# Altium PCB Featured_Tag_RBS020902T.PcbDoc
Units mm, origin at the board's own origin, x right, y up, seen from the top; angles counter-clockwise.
Board outline 33.22 x 33.22 mm, 2 copper layers (Top Layer, Bottom Layer); 37 components, 34 nets, 164 pads, 29 vias.
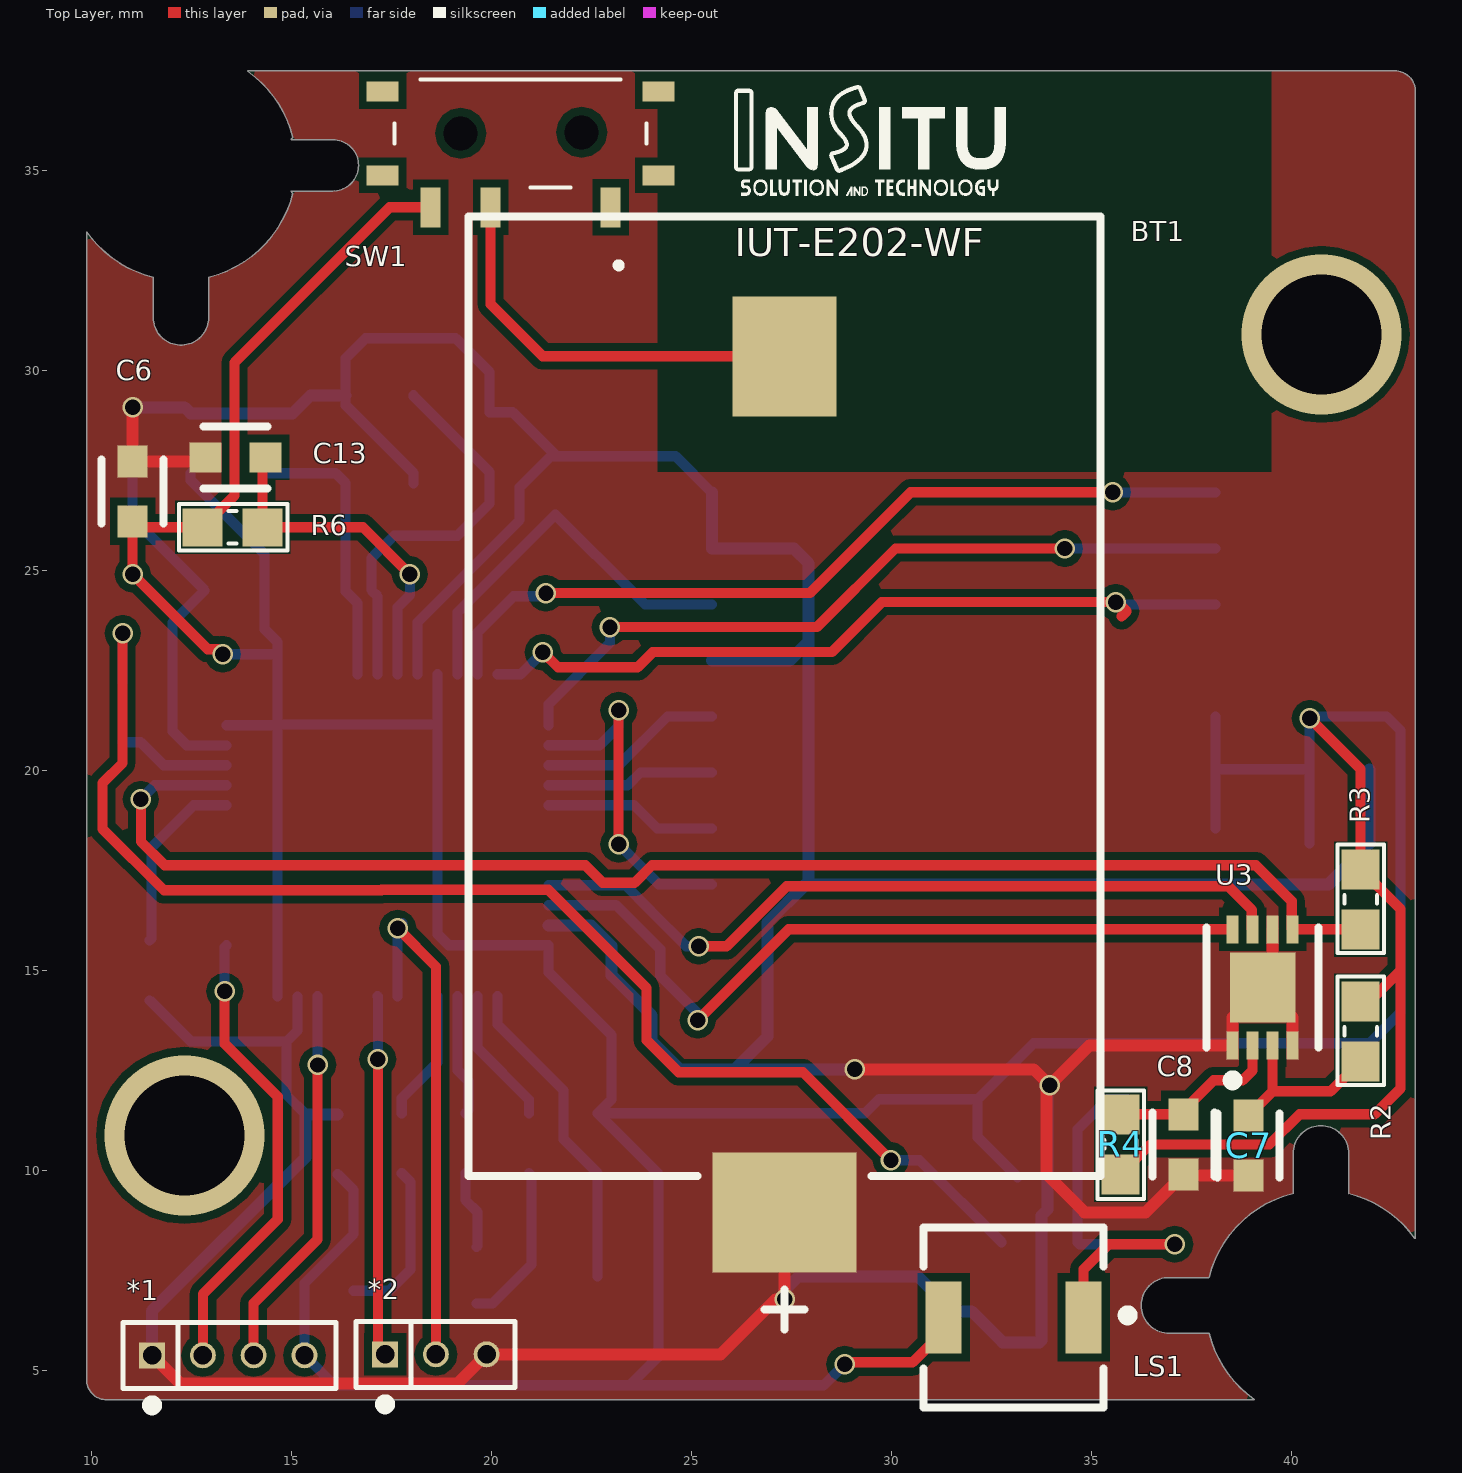
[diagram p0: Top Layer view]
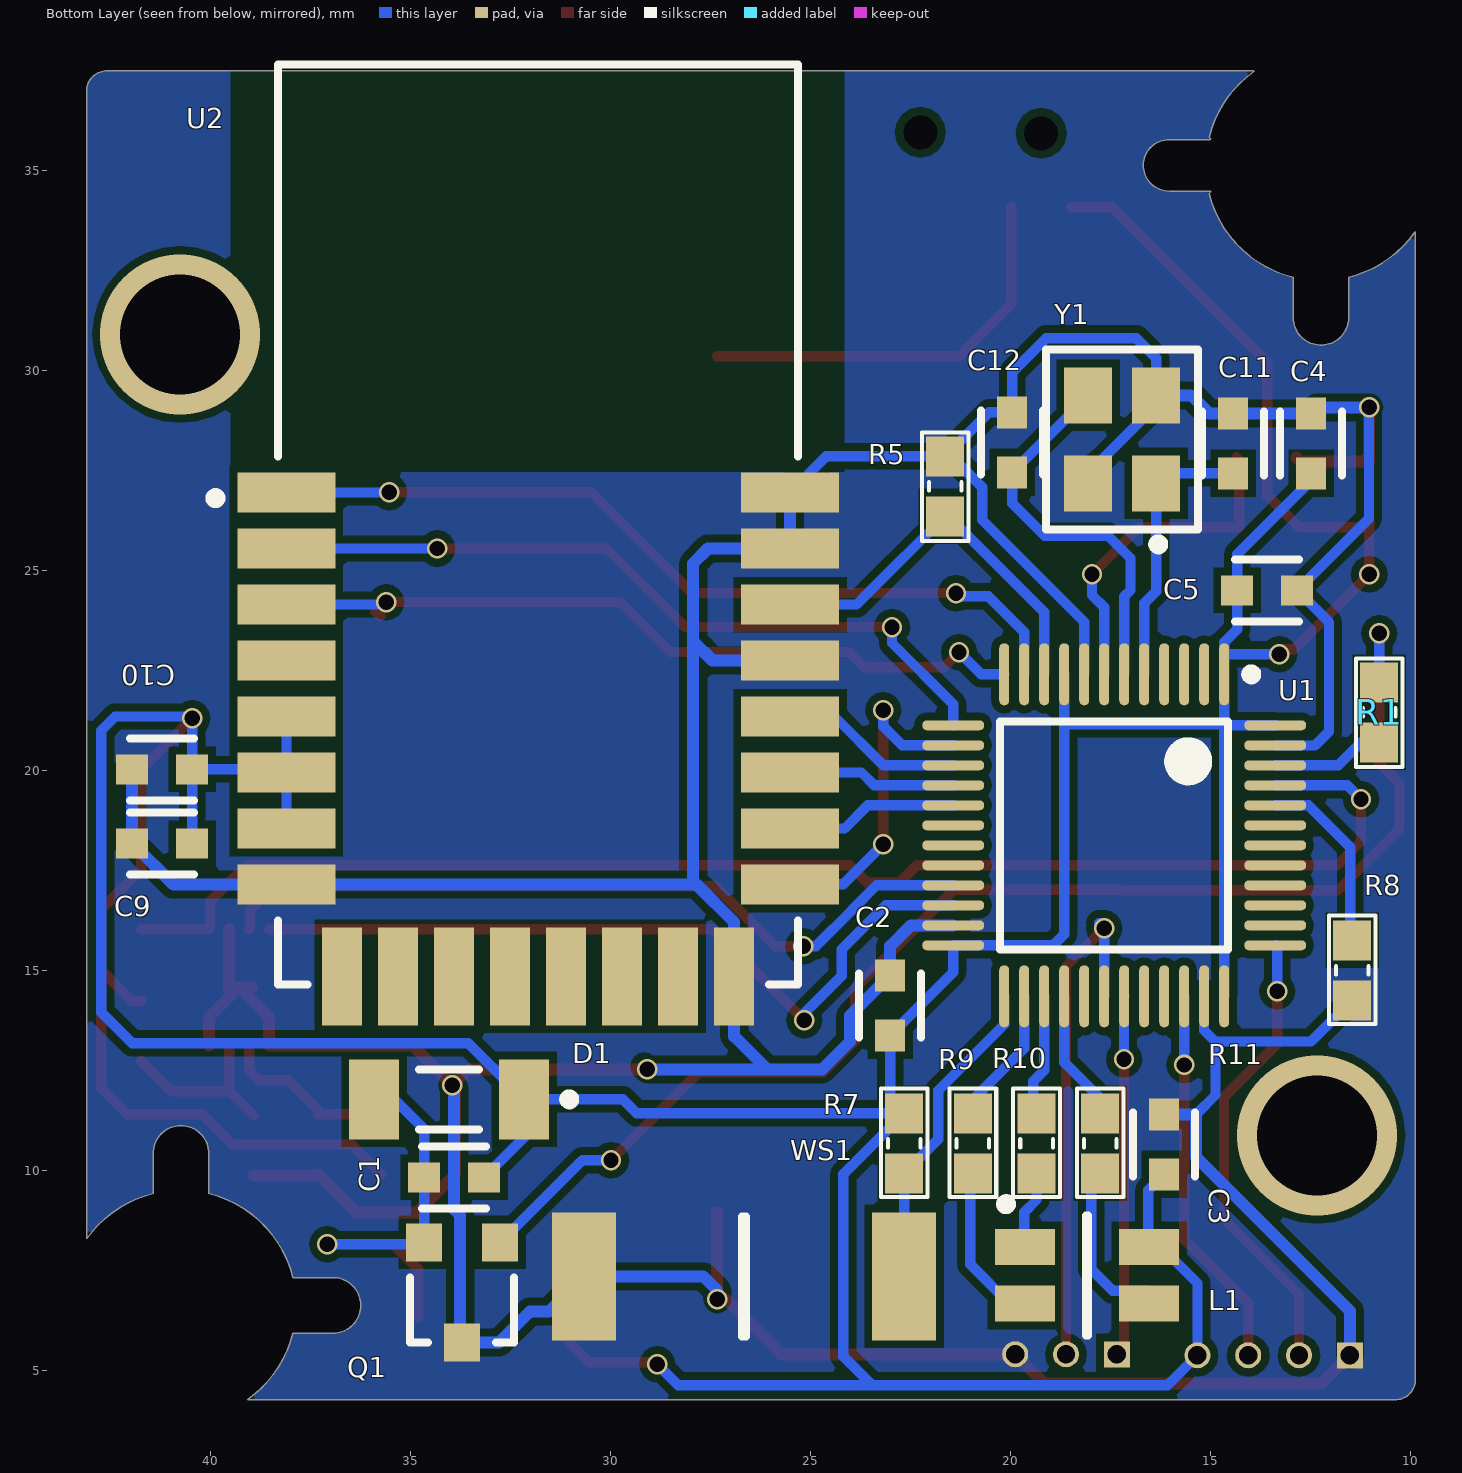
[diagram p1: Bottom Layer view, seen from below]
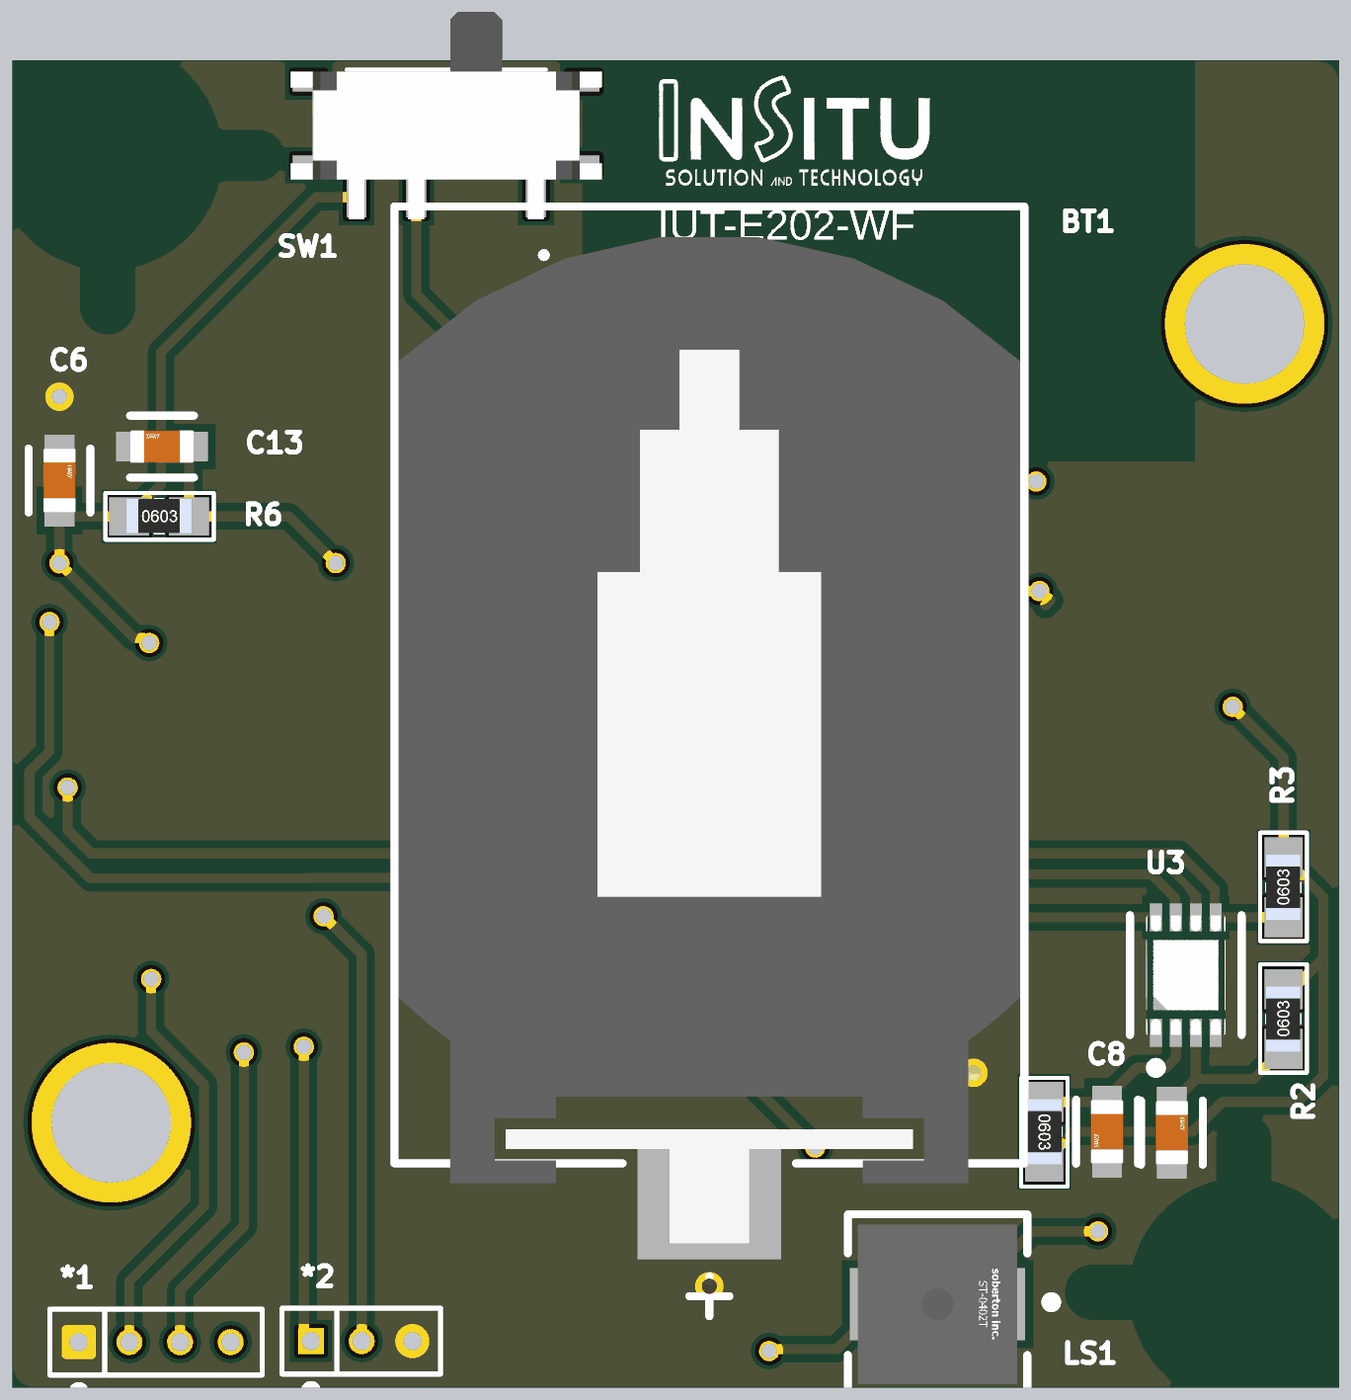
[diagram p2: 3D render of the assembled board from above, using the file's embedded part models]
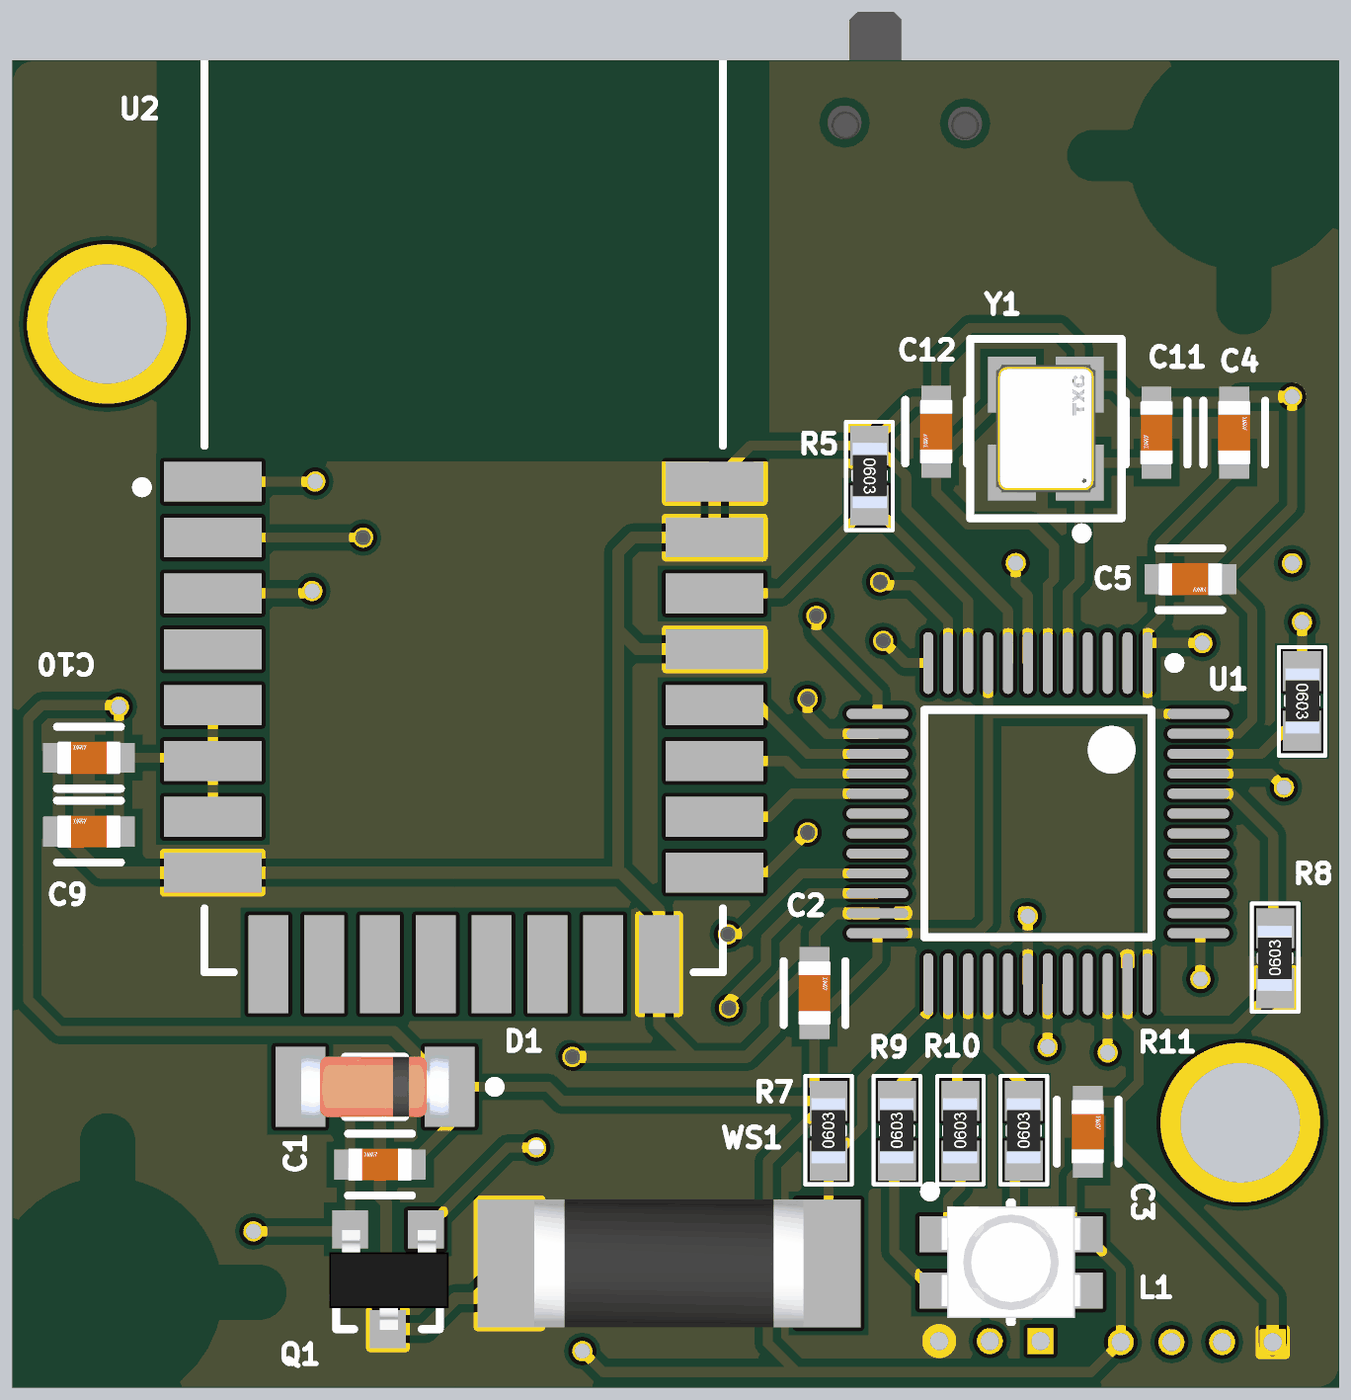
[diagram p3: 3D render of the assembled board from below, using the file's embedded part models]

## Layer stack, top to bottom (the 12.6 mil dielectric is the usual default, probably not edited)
Top Solder: solder mask 0.0102, Solder Resist, Dk 3.5
Top Layer: signal copper 0.0356
Dielectric 1: dielectric 0.32, FR-4, Dk 4.8
Bottom Layer: signal copper 0.0356
Bottom Solder: solder mask 0.0102, Solder Resist, Dk 3.5

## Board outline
9.871,4.769 ccw(c10.377,4.769) 10.377,4.263 10.378,4.263 39.055,4.263 39.06,4.275 cw(c40.732,6.624) 37.936,5.923 37.929,5.928 36.935,5.928 36.934,5.928 cw(c36.935,6.624) 36.935,7.319 37.929,7.319 37.936,7.325 cw(c40.732,6.624) 40.031,9.42 40.037,9.427 40.037,10.421 40.037,10.422 cw(c40.732,10.421) 41.428,10.421 41.428,9.427 41.433,9.42 cw(c40.732,6.624) 43.081,8.296 43.093,8.299 43.093,36.978 43.093,36.979 ccw(c42.587,36.979) 42.587,37.485 13.908,37.485 13.904,37.472 cw(c12.232,35.124) 15.028,35.828 cw(c7.741,41.518) 14.989,35.778 14.994,35.767 16.03,35.767 cw(c16.03,35.124) 16.673,35.124 cw(c16.03,35.124) 16.03,34.48 14.994,34.48 14.989,34.47 cw(c7.719,28.712) 15.028,34.42 cw(c12.232,35.124) 12.933,32.327 12.928,32.321 12.928,31.326 cw(c12.232,31.326) 11.537,31.326 11.537,32.321 11.531,32.327 cw(c12.232,35.124) 9.884,33.452 9.871,33.448

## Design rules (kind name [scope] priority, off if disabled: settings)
Clearance [All] p1: gap=0.2 ignorepadtopadclearanceinfootprint=FALSE
HoleSize [All] p1: absolutevalues=TRUE maxlimit=6 minlimit=0.102 maxpercent=80.000 minpercent=20.000
HoleToHoleClearance [Istext] p1: gap=0.254 allowstackedmicrovias=TRUE
MinimumSolderMaskSliver [TextHeight] p1: minsoldermaskwidth=0.254
PolygonConnect [All] p1: connectstyle=Direct reliefconductorwidth=0.254 reliefentries=4 polygonreliefangle="90 Angle" airgapwidth=0.254
RoutingVias [All] p1: holewidth=0.46 width=0.46 viastyle="Through Hole" minholewidth=0.46 minwidth=0.46 maxholewidth=0.46 maxwidth=0.46
SilkToSilkClearance [TextHeight] p1: silktosilkclearance=0.254
SilkToSolderMaskClearance [IsText] p1: minsilkscreentomaskgap=0.15 clearancetoexposedcopper=TRUE
SolderMaskExpansion [All] p1: expansion=0.102
Width [All] p1: maxlimit=0.9 minlimit=0.2 preferedwidth=0.6
25 further rules are at their usual default settings.

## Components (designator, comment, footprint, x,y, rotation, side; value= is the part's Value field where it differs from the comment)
*1 "JP 1x7 1.27mm" "JP 1x4 1.27mm" 11.485,5.375 r0 top
*2 "JP 1x3 1.27mm" "JP 1x3 1.27mm" 17.335,5.4 r0 top
BT1 "S8421-45R" FP-S8421-45R-MFG 27.325,21.85 r0 top
C1 "100pF" FP-0603-L_1_6_0_15-W_0_81-MFG 33.9,9.825 r0 bottom
C2 "100nF" FP-0603-L_1_6_0_15-W_0_81-MFG 23,14.125 r90 bottom
C3 "100nF" FP-0603-L_1_6_0_15-W_0_81-MFG 16.15,10.65 r90 bottom
C4 "100nF" FP-0603-L_1_6_0_15-W_0_81-MFG 12.475,28.175 r90 bottom
C5 "100nF" FP-0603-L_1_6_0_15-W_0_81-MFG 13.575,24.5 r180 bottom
C6 "4.7uF" FP-0603-L_1_6_0_15-W_0_81-MFG 11.025,26.975 r90 top
C7 "1uF" FP-0603-L_1_6_0_15-W_0_81-MFG 38.925,10.625 r90 top
C8 "10nF" FP-0603-L_1_6_0_15-W_0_81-MFG 37.3,10.65 r270 top
C9 "10uF" FP-0603-L_1_6_0_15-W_0_81-MFG 41.2,18.175 r0 bottom
C10 "100nF" FP-0603-L_1_6_0_15-W_0_81-MFG 41.2,20.025 r0 bottom
C11 "12pF" FP-0603-L_1_6_0_15-W_0_81-MFG 14.425,28.175 r270 bottom
C12 "12pF" FP-0603-L_1_6_0_15-W_0_81-MFG 19.95,28.2 r270 bottom
C13 "100nF" FP-0603-L_1_6_0_15-W_0_81-MFG 13.597,27.825 r180 top
D1 "LL4148-GS18" SOD-80 34.025,11.775 r0 bottom
L1 "LED 3528" "LED RGB 3528" 18.075,7.375 r180 bottom
LS1 "ST-0402T" FP-ST-0402T-MFG 33.05,6.325 r180 top value=17O
Q1 "HF" SOT23 33.7,6.95 r0 bottom value=C9014
R1 "1k" "tro smd 0603" 10.775,21.45 r270 bottom
R2 "1k" "tro smd 0603" 41.725,13.475 r90 top
R3 "4.7K" "tro smd 0603" 41.725,16.775 r90 top
R4 "1k" "tro smd 0603" 35.725,10.65 r270 top
R5 "10k" "tro smd 0603" 21.625,27.1 r270 bottom
R6 "10k" "tro smd 0603" 13.525,26.075 r0 top
R7 "10k" "tro smd 0603" 22.65,10.675 r90 bottom
R8 "10k" "tro smd 0603" 11.45,15 r90 bottom
R9 "100R" "tro smd 0603" 20.934,10.675 r90 bottom
R10 "150R" "tro smd 0603" 19.343,10.675 r90 bottom
R11 "100R" "tro smd 0603" 17.751,10.675 r90 bottom
SW1 "MSK-12C02" sw_msk_12c02 25.627,38.262 r180 top
U1 "STM32F103C8T6" STM-LQFP48_L 17.4,18.375 r270 bottom
U2 "DWM1000" DECW-DWM1000-24_V 31.8,26.145 r180 bottom
U3 "MAX17043G+T" FP-T823-1-MFG 39.275,14.575 r90 top
WS1 "RBS020902T" RBS020902T 26.65,7.35 r0 bottom
Y1 "8MHz" FP-7M-MFG 17.2,28.275 r90 bottom

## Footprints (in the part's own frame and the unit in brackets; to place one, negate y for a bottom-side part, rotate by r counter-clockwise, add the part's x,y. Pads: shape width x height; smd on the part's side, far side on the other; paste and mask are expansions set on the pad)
DECW-DWM1000-24_V [mm] "SMD, 24-Leads, Body 23x13mm, Pitch 1.4mm"
  rect 2.45x1 smd: 1(-6.295,0.8) 2(-6.295,-0.6) 3(-6.295,-2) 4(-6.295,-3.4) 5(-6.295,-4.8) 6(-6.295,-6.2) 7(-6.295,-7.6) 8(-6.295,-9) 17(6.295,-9) 18(6.295,-7.6) 19(6.295,-6.2) 20(6.295,-4.8) 21(6.295,-3.4) 22(6.295,-2) 23(6.295,-0.6) 24(6.295,0.8)
  rect 1x2.45 smd: 9(-4.9,-11.295) 10(-3.5,-11.295) 11(-2.1,-11.295) 12(-0.7,-11.295) 13(0.7,-11.295) 14(2.1,-11.295) 15(3.5,-11.295) 16(4.9,-11.295)
  silkscreen extent -8.2,-11.5 6.5,11.5, body extent -6.5,-11.5 6.5,11.5, height 4
FP-7M-MFG [mm]
  rect 1.4x1.2 smd paste+0 mask+0: 1(-1.1,-0.85) 2(1.1,-0.85) 3(1.1,0.85) 4(-1.1,0.85)
  silkscreen extent -2.75,-1.9 2.25,1.9, body extent -1.6,-1.25 1.6,1.25, height 0.8
FP-0603-L_1_6_0_15-W_0_81-MFG [mm]
  rect 0.8x0.75 smd paste+0 mask+0: 1(-0.75,0) 2(0.75,0)
  silkscreen extent -0.8,-0.77 0.8,0.77, body extent -0.8,-0.4 0.8,0.41, height 0.9
FP-S8421-45R-MFG [mm]
  rect 2.6x3 smd paste+0 mask+0: 1(0,8.5)
  rect 3.6x3 smd paste+0 mask+0: 2(0,-12.9)
  silkscreen extent -7.9,-15.83 7.9,12, body extent -8,-14.5 8,12.09, height 0.25
FP-ST-0402T-MFG [mm]
  rect 0.9x1.8 smd paste+0 mask+0: 1(-1.75,0) 2(1.75,0)
  silkscreen extent -2.98,-2.25 2.25,2.25, body extent -2.35,-2.35 2.35,2.35, height 0.25
FP-T823-1-MFG [mm]
  rect 0.7x0.3 smd paste+0 mask+0: 1(-1.45,0.75) 2(-1.45,0.25) 3(-1.45,-0.25) 4(-1.45,-0.75) 5(1.45,-0.75) 6(1.45,-0.25) 7(1.45,0.25) 8(1.45,0.75)
  rect 1.75x1.63 smd paste+0 mask+0: 9(0,0)
  silkscreen extent -2.45,-1.4 1.5,1.4, body extent -1.9,-1.12 1.9,1.12, height 0.25
"JP 1x3 1.27mm" [mm]
  rect 0.65x0.65 hole 0.46: 1(0,0)
  round 0.65 hole 0.46: 2(1.27,0) 3(2.54,0)
  silkscreen extent -0.73,-1.37 3.25,0.82
"JP 1x4 1.27mm" [mm]
  rect 0.65x0.65 hole 0.46: 1(0.025,0)
  round 0.65 hole 0.46: 2(1.295,0) 2(3.835,0) 3(2.565,0)
  silkscreen extent -0.7,-1.37 4.62,0.82
"LED RGB 3528" [mm] "Chip LED, 4-Leads, Body 2.8x3.5mm (max), Pitch 1.42mm, IPC Medium Density"
  rect 1.5x0.9 smd: 1(1.55,0.707) 2(1.55,-0.71) 3(-1.55,0.707) 4(-1.55,-0.707)
  silkscreen extent -2.16,-1.5 0.03,1.9, body extent -1.75,-1.4 1.75,1.4, height 1.87
RBS020902T [mm] "SENSOR SWITCH, 2-Leads, Body 6.75x3.20mm, IPC Medium Density"
  rect 1.6x3.2 smd: 1(-4,0) 2(4,0)
  Top Layer pour cut-out: 0.05,3.35
  silkscreen extent -0.05,-1.5 0.05,1.5, body extent -3.37,-1.6 3.38,1.6, height 3.2
SOD-80 [mm]
  rect 1.25x2 smd: 1(-1.875,0) 2(1.875,0)
  silkscreen extent -3.12,-0.75 0.75,0.75, body extent -1.85,-0.78 1.85,0.78, height 1.6
SOT23 [mm] "SOT23"
  rect 0.9x0.95 smd: 1(-0.95,-1.25) 2(0,1.25)
  rect 0.9x0.95 smd mask+0: 3(0.95,-1.25)
  silkscreen extent -1.3,-0.38 1.3,1.25, body extent -1.52,-1.23 1.48,1.27, height 1.06
STM-LQFP48_L [mm] "QFP, 48-Leads, Body 7x7mm, Pitch 0.5mm, IPC High Density"
  oval 1.55x0.25 smd: 1(-4.025,2.75) 2(-4.025,2.25) 3(-4.025,1.75) 4(-4.025,1.25) 5(-4.025,0.75) 6(-4.025,0.25) 7(-4.025,-0.25) 8(-4.025,-0.75) 9(-4.025,-1.25) 10(-4.025,-1.75) 11(-4.025,-2.25) 12(-4.025,-2.75) 25(4.025,-2.75) 26(4.025,-2.25) 27(4.025,-1.75) 28(4.025,-1.25) 29(4.025,-0.75) 30(4.025,-0.25) 31(4.025,0.25) 32(4.025,0.75) 33(4.025,1.25) 34(4.025,1.75) 35(4.025,2.25) 36(4.025,2.75)
  oval 0.25x1.55 smd: 13(-2.75,-4.025) 14(-2.25,-4.025) 15(-1.75,-4.025) 16(-1.25,-4.025) 17(-0.75,-4.025) 18(-0.25,-4.025) 19(0.25,-4.025) 20(0.75,-4.025) 21(1.25,-4.025) 22(1.75,-4.025) 23(2.25,-4.025) 24(2.75,-4.025) 37(2.75,4.025) 38(2.25,4.025) 39(1.75,4.025) 40(1.25,4.025) 41(0.75,4.025) 42(0.25,4.025) 43(-0.25,4.025) 44(-0.75,4.025) 45(-1.25,4.025) 46(-1.75,4.025) 47(-2.25,4.025) 48(-2.75,4.025)
  silkscreen extent -4.15,-2.85 2.85,3.55, body extent -3.5,-3.5 3.5,3.5, height 1.6
sw_msk_12c02 [mm]
  rect 0.5x1 smd: A1(2.652,4.187) B1(5.652,4.187) C1(7.152,4.187)
  round 0.425 hole 0.85 unplated: MH1(3.378,2.311) MH2(6.402,2.337)
  rect 0.8x0.5 smd: MP1(8.352,3.387) MP2(8.352,1.287) MP3(1.452,1.287) MP4(1.452,3.387)
  silkscreen extent 1.75,0.99 8.05,5.69, body extent 1,-0.46 8.8,4.74, height 1.46
"tro smd 0603" [mm] "Chip Capacitor, 2-Leads, Body 1,60x0,80mm, IPC Medium Density"
  rect 1x0.95 smd mask+0.076: 1(-0.75,0) 2(0.75,0)
  silkscreen extent -1.35,-0.58 1.37,0.58, body extent -0.82,-0.42 0.82,0.43, height 0.44

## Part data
BT1: library part CMP-2000-07028-3, "BATTERY HOLDER COIN 20MM SMD", Case/Package=SMD/SMT, Max Operating Temperature=105°C, Min Operating Temperature=-40°C, Package Quantity=500
C1 C2 C3 C4 C5 C6 C7 C8 C9 C10 C11 C12 C13: library part CMP-2006-04515-2, "General Purpose Ceramic Capacitor, 0603, 33nF, 5%, X7R, 15%, 16V", Capacitance=33nF, Case/Package=0603, Case Code (Metric)=1608, Dielectric=X7R, Max Operating Temperature=125°C, Min Operating Temperature=-55°C, Package Quantity=4000, Tolerance=5%, Voltage Rating=16V
D1: "Vishay LL4148-GS18 Switching Diode, 300mA, 2-Pin MiniMELF", Manufacturer_Name=Vishay, Mouser Part Number=78-LL4148-GS18
L1: library part "LED 3528 RGB", "Dán"
LS1: library part CMP-247804-000001-1, "AUDIO MAGNETIC XDCR 2-4V SMD", Current=90mA, Frequency=4kHz, Manufacturer="Soberton Inc.", Max Supply Voltage=4V, Min Supply Voltage=2V, Operating Supply Voltage=3V, Resistance=17O, Temperature="-30°C to +70°C", Temperature Range High=+70°C, Temperature Range Low=-30°C
Q1: library part "C1815 HF SMD", "NPN transistor"
R1 R2 R3 R4: library part "Tro 0603 5% 1k", "Dán"
R5 R6 R7 R8: library part "Tro 0603 5% 10k", "Dán"
R9 R11: library part "Tro 0603 5% 100R", "Dán"
R10: library part "Tro 0603 5% 150R", "Dán"
U1: library part CMP-0237-00215-3, "ARM Cortex-M3 32-bit MCU, 64 KB Flash, 20 KB Internal RAM, 37 I/Os, 48-pin LQFP, -40 to 85 degC, Tray", I/Os (High Current)=37, Operating Frequency(F) (Processor speed) (MHz)=72, Supply Voltage(Vcc) min (V)=2
U2: library part CMP-2000-05094-1, "DW M1000 IEEE 802.15.4 -2011 UWB Transceiver Module", Current - Receiving=64mA, Current - Transmitting=31mA, Frequency=3.5GHz~6.5GHz, Manufacturer=Decawave, Operating Temperature=-40degC~85degC, Package / Case=Module, Power - Output=-, Standard Package=500, Voltage - Supply=2.8V~3.6V
U3: library part CMP-05715-000066-1, "IC 2-WIRE FG MODEL GAUGE LO BATT", Manufacturer=Maxim, Max Supply Voltage=4.5V, Min Supply Voltage=2.5V, Nominal Supply Current=50uA, Package=T823-1, Temperature="-20°C to +70°C", Temperature Range High=+70°C, Temperature Range Low=-20°C
Y1: library part CMP-18717-000290-1, "Crystal 26MHz, 30ppm, 18pF, 50O", Case/Package=SMD/SMT, ESR (Equivalent Series Resistance)=60R, Frequency=26MHz, Frequency Stability=30ppm, Load Capacitance=18pF, Max Operating Temperature=70°C, Min Operating Temperature=-20°C, Package Quantity=3000

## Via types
v1: diameter 0.508, hole 0.381, Top Layer to Bottom Layer, 27 vias
v2: diameter 4, hole 3, Top Layer to Bottom Layer, 2 vias

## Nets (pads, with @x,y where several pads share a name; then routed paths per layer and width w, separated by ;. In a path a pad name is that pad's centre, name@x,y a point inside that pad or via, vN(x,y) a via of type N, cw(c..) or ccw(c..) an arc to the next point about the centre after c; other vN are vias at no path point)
+3: *1.2@15.32,5.375 C1.1 C2.1 C3.1 C4.1 C5.1 C6.1 C9.1 C10.1 D1.1 L1.1 LS1.2 R2.2 R3.2 R4.2 R6.1 R7.2 SW1.C1 U1.1 U1.9 U1.24 U1.36 U1.48 U2.5 U2.6 U2.7 | length 143.1
  Top Layer w0.254: v1@13.325,22.9 v1(13.275,22.9) 13.15,23.025 12.9,23.025 v1(11.025,24.9) C6.1 11.175,26.075 R6.1 13.574,26.874 13.574,30.199 17.45,34.075 SW1.C1 ; v1(28.825,5.15) 28.875,5.2 30.525,5.2 31.3,5.975 LS1.2 ; R4.2 36.473,10.648 39.448,10.648 40.2,11.4 42.075,11.4 42.725,12.05 42.725,15 ; v1(40.45,21.3) 41.725,20.025 R3.2 42.725,16.525 42.725,15 ; R2.2 41.95,14.225 42.725,15
  Bottom Layer w0.254: C4.1 12.475,27.25 14.325,25.4 C5.1 14.325,23.525 14.65,23.2 U1.1@14.65,22.875 ; v1(13.275,22.9) 14.625,22.9 U1.1@14.65,22.875 ; U1.48 14.65,21.125 ; U1.36 14.65,21.125 ; C3.1 16.55,9.5 16.55,8.408 15.32,7.178 15.32,5.375 16.07,4.625 23.45,4.625 ; U1.9 18.65,21.145 ; v1(28.825,5.15) 28.3,4.625 23.45,4.625 ; C1.1 32.15,10.825 D1.1 ; U2.7 U2.6 ; U2.5 U2.6 ; C9.1 C10.1 ; 14.65,21.125 14.65,21.145 ; 14.65,21.145 U1.1 U1.1@14.65,22.875 ; 14.65,21.145 18.65,21.145 ; 18.65,21.145 18.65,15.9 18.925,15.625 U1.24 21.425,14.95 C2.1 23,11.775 R7.2 ; R7.2 29.335,11.425 29.685,11.775 D1.1 ; R7.2 24.175,9.9 24.175,5.35 23.45,4.625 ; D1.1 33.55,13.175 41.95,13.175 42.725,13.95 42.725,20.995 42.375,21.345 40.495,21.345 v1(40.45,21.3) C10.1 ; U2.6 38.175,20.025 C10.1
BLUE: R11.2 U1.28 | length 3.3
  Bottom Layer w0.254: R11.2 17.751,11.801 18.65,12.7 U1.28
BOOT0: R8.2 U1.44 | length 4.7
  Bottom Layer w0.254: R8.2 11.5,15.8 11.5,18.075 12.55,19.125 U1.44
BUZZER: R1.2 U1.46 | length 2.8
  Bottom Layer w0.254: R1.2 11.225,20.7 11.8,20.125 U1.46
CLK: *1.2@12.78,5.375 U1.37 | length 11.6
  Top Layer w0.254: *1.2@12.78,5.375 12.78,6.905 14.652,8.777 14.652,11.839 13.325,13.166 v1(13.325,14.475)
  Bottom Layer w0.254: v1(13.325,14.475) 13.325,15.575 U1.37
DIO: *1.3 U1.34 | length 9.6
  Top Layer w0.254: *1.3 14.05,6.675 15.65,8.275 v1(15.65,12.635)
  Bottom Layer w0.254: v1@15.65,12.635 U1.34
GND: *1.1 *2.3 BT1.2 C2.2 C3.2 C4.2 C5.2 C6.2 C7.1 C8.2 C9.2 C10.2 C11.1 C12.1 C13.2 Q1.2 R5.1 R8.1 U1.8 U1.23 U1.35 U1.47 U2.8 U2.16 U2.21 U2.23 U2.24 U3.1 U3.4 U3.6 U3.9 WS1.2 Y1.2 Y1.4 | length 160.6
  Top Layer w0.3: v1(11.025,29.075) 11.025,27.875 11.1,27.8 C6.2 12.747,27.725 C13.2 ; *1.1 12.21,4.675 19.15,4.675 *2.3 25.725,5.4 27.1,6.775 v1(27.325,6.775) BT1.2 ; v1(29.075,12.525) 33.55,12.525 v1(33.95,12.125) ; C7.1 37.325,9.875 C8.2 36.35,8.95 34.825,8.95 33.875,9.9 33.875,12.05 v1(33.95,12.125) ; U3.9@38.95,14.575 U3.9 ; U3.6 39.525,14.575 U3.9 ; U3.4 40.025,13.825 U3.9 ; v1(33.95,12.125) 34.95,13.125 U3.1 38.525,13.825 U3.9
  Bottom Layer w0.25: v1(11.025,29.075) 11.025,26.3 C5.2 12.025,23.7 12.025,20.975 12.375,20.625 U1.47 ; R8.1 12.475,13.225 14.868,13.225 ; U1.35 15.15,13.493 14.875,13.218 14.868,13.225 ; 15.35,11.4 14.868,11.882 14.868,13.225
  Bottom Layer w0.254: Y1.4 18.05,27.425 16.35,29.125 Y1.2 16.35,30.3 16.85,30.8 19.1,30.8 19.95,29.95 C12.1 20.525,28.95 R5.1 ; U1.8 18.15,23.709 20.7,26.259 20.7,27.075 21.475,27.85 R5.1 ; U2.24 24.6,27.85 R5.1
  Bottom Layer w0.3: v1(11.025,29.075) 12.325,29.075 C4.2 C11.1 15.025,28.925 15.475,29.375 Y1.2 ; *1.1 11.51,6.485 15.35,10.325 15.35,11.4 C3.2 ; U1.23 22.481,16.125 23,15.606 C2.2 24,13.875 24,13.225 24.7,12.525 26.075,12.525 ; U2.21 27.445,22.745 27.925,23.225 ; U2.24 U2.23 27.555,25.545 27.925,25.175 27.925,23.225 ; v1(27.325,6.775) 27.325,7 27.675,7.35 WS1.2 31.525,6.475 32,6.475 32.775,5.7 Q1.2 33.75,5.75 33.75,8.875 33.9,9.025 33.9,12.075 v1(33.95,12.125) ; v1@29.15,12.6 v1(29.075,12.525) 26.075,12.525 ; C10.2 C9.2 40.92,17.145 U2.8 28,17.145 ; 26.075,12.525 26.9,13.35 U2.16 26.9,16.2 27.845,17.145 28,17.145 ; 27.925,23.225 27.925,17.22 28,17.145
GREEN: R9.2 U1.26 | length 3.5
  Bottom Layer w0.254: U1.26 19.65,13.05 20.934,11.766 R9.2
INTERRUPT_PIN: R3.1 U1.45 U3.5 | length 35.5
  Top Layer w0.254: v1(11.23,19.278) 11.23,18.22 11.825,17.625 22.34,17.625 22.777,17.188 23.573,17.188 24.01,17.625 39.105,17.625 40.002,16.728 40.002,16.048 U3.5 R3.1
  Bottom Layer w0.254: v1(11.23,19.278) 11.577,19.625 U1.45
NetBT1_1: BT1.1 SW1.B1 | length 10.3
  Top Layer w0.254: SW1.B1 19.975,31.65 21.275,30.35 BT1.1
NetC1_2: C1.2 D1.2 LS1.1 Q1.3 | length 10.6
  Top Layer w0.254: LS1.1 34.8,7.525 35.425,8.15 v1(37.075,8.15)
  Bottom Layer w0.254: D1.2 35.4,11.775 34.65,11.025 C1.2 Q1.3 34.7,8.15 v1(37.075,8.15)
NetC7_2: C7.2 R2.1 U3.3 | length 4.5
  Top Layer w0.254: C7.2 39.525,11.975 ; U3.3 39.525,11.975 ; R2.1 40.975,11.975 39.525,11.975
NetC8_1: C8.1 R4.1 U3.2 | length 4.4
  Top Layer w0.254: R4.1 C8.1 37.3,11.5 38.05,12.25 38.775,12.25 39.025,12.5 U3.2
NetL1_2: L1.2 R11.1 | length 4.1
  Bottom Layer w0.254: L1.2@16.55,6.99 17.44,6.99 17.975,7.525 17.975,9.701 R11.1
NetL1_3: L1.3 R10.1 | length 2
  Bottom Layer w0.254: R10.1 19.343,9.257 19.65,8.95 19.65,8.107 L1.3
NetL1_4: L1.4 R9.1 | length 4.1
  Bottom Layer w0.254: L1.4 20.018,6.667 21,7.65 21,9.859 R9.1
NetQ1_1: Q1.1 R1.1 | length 33.9
  Top Layer w0.254: v1(10.775,23.425) 10.775,20.184 10.268,19.677 10.268,18.54 11.808,17 17.24,17 17.252,17.012 21.413,17.012 23.875,14.55 23.875,13.25 24.675,12.45 27.784,12.45 v1(29.981,10.253)
  Bottom Layer w0.254: R1.1 v1(10.775,23.425) v1@10.775,23.45 ; v1@29.981,10.306 v1(29.981,10.253) 30.697,10.253 Q1.1
OSCIN: C11.2 U1.5 Y1.1 | length 6.9
  Bottom Layer w0.254: C11.2 16.1,27.425 Y1.1 16.35,24.475 16.65,24.175 U1.5
OSCOUT: C12.2 U1.6 Y1.3 | length 10
  Bottom Layer w0.254: U1.6 17.15,24.349 16.993,24.505 16.993,25.302 17.557,25.866 19.141,25.866 19.95,26.675 C12.2 18.05,29.35 Y1.3
RED: R10.2 U1.27 | length 3.1
  Bottom Layer w0.254: U1.27 19.15,12.5 19.425,12.225 19.425,11.508 R10.2
RESET: C13.1 R6.2 U1.7 | length 8.6
  Top Layer w0.254: C13.1 14.275,27.753 R6.2 16.784,26.075 v1(17.955,24.904)
  Bottom Layer w0.254: U1.7 17.65,24.075 17.955,24.38 v1(17.955,24.904)
RX: *2.1 U1.31 | length 9.1
  Top Layer w0.254: v1(17.155,12.778) 17.155,5.58 *2.1
  Bottom Layer w0.254: U1.31 17.155,14.345 v1(17.155,12.778) v1@17.155,12.655
SCL_MAX: U1.21 U3.7 | length 19.6
  Top Layer w0.254: v1(25.175,15.6) 25.875,15.6 27.375,17.1 38.412,17.1 39.002,16.51 39.002,16.048 U3.7
  Bottom Layer w0.254: U1.21 23.345,17.125 23.953,16.517 23.953,16.51 24.863,15.6 v1(25.175,15.6)
SDA_MAX: U1.22 U3.8 | length 19.7
  Top Layer w0.254: v1(25.15,13.75) 27.425,16.025 U3.8
  Bottom Layer w0.254: U1.22 23.112,16.625 24.213,15.524 24.213,14.862 25.15,13.925 v1(25.15,13.75)
SW_R: R7.1 U1.25 WS1.1 | length 8
  Bottom Layer w0.254: U1.25 20.15,13.646 21.8,11.996 21.8,10.775 R7.1 WS1.1
TX: *2.2 U1.30 | length 12.9
  Top Layer w0.254: v1(17.65,16.05) 18.605,15.095 *2.2
  Bottom Layer w0.254: U1.30 v1(17.65,16.05) v1@17.775,16.175
UWBCLK: U1.15 U2.20 | length 4.6
  Bottom Layer w0.254: U1.15 23.175,20.125 24.395,21.345 U2.20
UWBCS: U1.14 U2.17 | length 8.4
  Top Layer w0.254: v1(23.175,18.15) v1(23.175,21.5)
  Bottom Layer w0.254: U1.14 22.7,20.625 23.175,21.1 v1(23.175,21.5) ; v1(23.175,18.15) 24.175,17.15 25.5,17.15 U2.17
UWBEXT: U1.11 U2.1 | length 21.1
  Top Layer w0.254: v1(21.356,24.429) 27.954,24.429 30.475,26.95 v1(35.525,26.95) v1@35.55,26.925
  Bottom Layer w0.254: U1.11 19.65,23.45 20.55,24.35 21.318,24.35 21.396,24.429 v1(21.356,24.429) ; v1(35.525,26.95) 35.53,26.945 U2.1
UWBIRQ: R5.2 U1.10 U2.22 | length 9.8
  Bottom Layer w0.254: U1.10 19.15,23.95 21.588,26.388 21.593,26.393 21.63,26.355 23.598,24.387 23.84,24.145 U2.22
UWBMISO: U1.16 U2.19 | length 4.2
  Bottom Layer w0.254: U1.16 23.4,19.625 23.72,19.945 U2.19
UWBMOSI: U1.17 U2.18 | length 4.3
  Bottom Layer w0.254: U1.17 23.56,19.125 24.14,18.545 U2.18
UWBRST: U1.12 U2.3 | length 19.7
  Top Layer w0.254: v1@21.375,22.95 21.371,22.954 v1(21.279,22.954) 21.657,22.575 23.65,22.575 24.029,22.954 28.504,22.954 29.754,24.204 v1(35.6,24.204) 35.646,24.204 35.875,23.975 35.75,23.85
  Bottom Layer w0.254: U1.12 20.725,22.4 v1(21.279,22.954) ; v1(35.6,24.204) 35.659,24.145 U2.3
UWBWAKEUP: U1.13 U2.2 | length 19.1
  Top Layer w0.254: v1(22.956,23.579) 28.129,23.579 30.095,25.545 v1(34.325,25.545)
  Bottom Layer w0.254: U1.13 21.425,21.65 22.956,23.181 v1(22.956,23.579) 22.996,23.579 v1@22.975,23.6 ; v1(34.325,25.545) U2.2
pads on no net: SW1.A1 SW1.MH1 SW1.MH2 SW1.MP1 SW1.MP2 SW1.MP3 SW1.MP4 U1.2 U1.3 U1.4 U1.18 U1.19 U1.20 U1.29 U1.32 U1.33 U1.38 U1.39 U1.40 U1.41 U1.42 U1.43 U2.4 U2.9 U2.10 U2.11 U2.12 U2.13 U2.14 U2.15
copper on no net:
  other v2: 12.325,10.875 40.75,30.9

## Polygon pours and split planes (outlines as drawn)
GND on Bottom Layer "GND_L02_P001" (solid, pour order 1): 9.871,4.769 ccw(c10.377,4.769) 10.377,4.263 10.378,4.263 39.055,4.263 39.06,4.275 cw(c40.732,6.624) 37.936,5.923 37.929,5.928 36.935,5.928 36.934,5.928 cw(c36.935,6.624) 36.935,7.319 37.929,7.319 37.936,7.325 cw(c40.732,6.624) 40.031,9.42 40.037,9.427 40.037,10.421 40.037,10.422 cw(c40.732,10.421) 41.428,10.421 41.428,9.427 41.433,9.42 cw(c40.732,6.624) 43.081,8.296 43.093,8.299 43.093,36.978 43.093,36.979 ccw(c42.587,36.979) 42.587,37.485 13.908,37.485 13.904,37.472 cw(c12.232,35.124) 15.028,35.828 cw(c7.741,41.518) 14.989,35.778 14.994,35.767 16.03,35.767 cw(c16.03,35.124) 16.673,35.124 cw(c16.03,35.124) 16.03,34.48 14.994,34.48 14.989,34.47 cw(c7.719,28.712) 15.028,34.42 cw(c12.232,35.124) 12.933,32.327 12.928,32.321 12.928,31.326 cw(c12.232,31.326) 11.537,31.326 11.537,32.321 11.531,32.327 cw(c12.232,35.124) 9.884,33.452 9.871,33.448
GND on Top Layer "GND_L01_P000" (solid, pour order 0): 9.871,4.769 ccw(c10.377,4.769) 10.377,4.263 10.378,4.263 39.055,4.263 39.06,4.275 cw(c40.732,6.624) 37.936,5.923 37.929,5.928 36.935,5.928 36.934,5.928 cw(c36.935,6.624) 36.935,7.319 37.929,7.319 37.936,7.325 cw(c40.732,6.624) 40.031,9.42 40.037,9.427 40.037,10.421 40.037,10.422 cw(c40.732,10.421) 41.428,10.421 41.428,9.427 41.433,9.42 cw(c40.732,6.624) 43.081,8.296 43.093,8.299 43.093,36.978 43.093,36.979 ccw(c42.587,36.979) 42.587,37.485 13.908,37.485 13.904,37.472 cw(c12.232,35.124) 15.028,35.828 cw(c7.741,41.518) 14.989,35.778 14.994,35.767 16.03,35.767 cw(c16.03,35.124) 16.673,35.124 cw(c16.03,35.124) 16.03,34.48 14.994,34.48 14.989,34.47 cw(c7.719,28.712) 15.028,34.42 cw(c12.232,35.124) 12.933,32.327 12.928,32.321 12.928,31.326 cw(c12.232,31.326) 11.537,31.326 11.537,32.321 11.531,32.327 cw(c12.232,35.124) 9.884,33.452 9.871,33.448

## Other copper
Top Layer:
  pour cut-out: 24.183,37.485 24.14,37.442 24.14,27.45 39.5,27.45 39.5,37.485
  pour cut-out: 24.14,27.45
Bottom Layer:
  pour cut-out: 24.183,37.485 24.14,37.442 24.14,27.45 39.5,27.45 39.5,37.485
  pour cut-out: 24.175,37.5

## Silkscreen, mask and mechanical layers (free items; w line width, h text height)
Top Overlay:
  drawing of 27 lines, arcs and shapes, not listed
  text "IUT-E202-WF" at 26.075,32.608 h1.2
Mechanical 1:
  lines w0.508: 9.871,4.769 ccw(c10.377,4.769) 10.377,4.263 ; 9.871,4.769 ccw(c9.878,4.769) 9.871,4.769 ; 9.871,4.769 9.871,33.448 cw(c9.878,33.448) 9.884,33.452 ; 9.884,33.452 ccw(c12.232,35.124) 11.531,32.327 ; 9.884,33.452 ccw(c12.232,35.124) 9.884,33.452 ; 9.884,33.452 9.884,33.452 ; 10.377,4.263 ccw(c10.377,4.769) 10.378,4.263 ; 10.378,4.263 10.378,4.263 ; 10.378,4.263 39.055,4.263 39.056,4.262 ; 11.531,32.327 cw(c11.53,32.321) 11.537,32.321 11.537,31.326 ccw(c12.232,31.326) 12.928,31.326 12.928,32.321 cw(c12.935,32.321) 12.933,32.327 ; 11.531,32.327 11.531,32.327 ; 12.933,32.327 ccw(c12.232,35.124) 15.028,34.42 ccw(c7.719,28.712) 14.989,34.47 ; 12.933,32.327 cw(c12.232,35.124) 12.933,32.327 12.933,32.327 ; 13.904,37.472 cw(c13.908,37.478) 13.908,37.485 42.587,37.485 ; 13.904,37.472 cw(c12.232,35.124) 15.028,35.828 cw(c7.741,41.518) 14.989,35.778 ccw(c14.994,35.774) 14.987,35.774 ccw(c14.994,35.774) 14.994,35.767 16.03,35.767 ; 13.904,37.472 13.904,37.472 ; 14.989,34.47 cw(c14.994,34.474) 14.994,34.48 16.03,34.48 ccw(c16.03,35.124) 16.673,35.124 ccw(c16.03,35.124) 16.03,35.767 ; 14.989,34.47 14.989,34.47 ; 16.03,35.767 ccw(c16.03,35.774) 16.03,35.767 ; 16.03,35.767 ccw(c16.03,35.124) 16.03,35.767 ; 16.03,35.767 16.03,35.767 ; 36.935,5.928 ccw(c36.935,5.921) 36.934,5.928 ; 36.934,5.928 cw(c36.935,6.624) 36.935,7.319 37.929,7.319 ccw(c37.929,7.326) 37.936,7.325 ; 36.935,5.928 37.929,5.928 cw(c37.929,5.921) 37.936,5.923 ; 37.936,5.923 ccw(c40.732,6.624) 39.06,4.275 ; 37.936,5.923 ccw(c40.732,6.624) 37.936,5.923 ; 37.936,5.923 37.936,5.923 ; 37.936,7.325 cw(c40.732,6.624) 40.031,9.42 ; 37.936,7.325 37.936,7.325 ; 39.056,4.262 ccw(c39.06,4.268) 39.056,4.262 ; 39.056,4.262 39.057,4.261 ; 39.057,4.261 ccw(c39.061,4.267) 39.057,4.261 ; 39.057,4.261 39.06,4.259 ccw(c39.064,4.265) 39.071,4.265 ccw(c39.064,4.265) 39.068,4.27 39.065,4.272 ; 39.06,4.275 ccw(c39.057,4.27) 39.06,4.275 ; 39.06,4.275 ccw(c39.057,4.27) 39.06,4.275 ; 39.06,4.275 ccw(c40.732,6.624) 39.061,4.275 ; 39.06,4.275 39.063,4.273 cw(c39.06,4.268) 39.063,4.273 39.065,4.272 ; 39.06,4.275 39.06,4.275 ; 39.06,4.275 39.061,4.275 ; 39.06,4.275 39.06,4.275 ; 39.065,4.272 39.065,4.272 ; 40.032,9.42 ccw(c40.732,6.624) 40.031,9.42 ; 40.031,9.42 ccw(c40.03,9.427) 40.037,9.427 40.037,10.421 ; 40.031,9.42 40.032,9.42 ; 40.037,10.421 ccw(c40.03,10.421) 40.037,10.422 ; 40.037,10.422 ccw(c40.732,10.421) 40.037,10.421 ; 40.037,10.422 cw(c40.732,10.421) 41.428,10.421 41.428,9.427 ccw(c41.435,9.427) 41.433,9.42 ; 40.037,10.421 40.037,10.422 ; 41.433,9.42 cw(c40.732,6.624) 43.081,8.296 ; 41.433,9.42 41.433,9.42 ; 42.587,37.485 cw(c42.587,36.979) 43.093,36.979 ; 42.587,37.485 ccw(c42.587,36.979) 42.587,37.485 ; 42.587,37.485 ccw(c42.587,37.478) 42.587,37.485 ; 42.587,37.485 42.587,37.485 ; 42.587,37.485 42.587,37.485 ; 43.081,8.296 ccw(c40.732,6.624) 43.081,8.296 ; 43.081,8.296 ccw(c43.086,8.299) 43.093,8.299 43.093,36.978 ; 43.081,8.296 43.081,8.296 ; 43.093,36.978 ccw(c43.086,36.978) 43.093,36.979 ; 43.093,36.979 ccw(c42.587,36.979) 43.093,36.979 ; 43.093,36.978 ccw(c42.587,36.979) 43.093,36.979 ; 43.093,36.978 43.093,36.979
Mechanical 4:
  drawing of 610 lines, arcs and shapes, not listed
